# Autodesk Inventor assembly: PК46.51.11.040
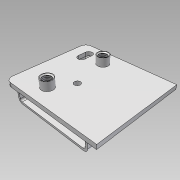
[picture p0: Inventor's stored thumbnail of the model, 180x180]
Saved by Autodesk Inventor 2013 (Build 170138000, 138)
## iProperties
Shininess: 64.0
Length Units: 11269
Angle Units: 11279
Time Units: 11290
Mass Units: 11283
Length Display Precision: 3
Angle Display Precision: 2
Compacted: True
Created: 2005-02
Part Number: PК46.51.11.040
Document SubType Name: Assembly
Designer: =<Author>
Manufacturer: Standard
Standards Organization: Custom
Description: Reliance Lock
Mass: 287.102 g
Surface Area: 258.181 cm^2
Volume: 36.5269 cm^3
Density: 7.86 g/cm^3
Density: 0.0
Volumn: 0.0
Area: 0.0
PropertySet Name: Model Information
Control State: 0
Master: False
Checked Out: False
Checked Out Date: 2008-10-15
Last Check In Date: 2008-10-15
Author: PVitaliy
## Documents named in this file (4)
- Y:\Dropbox\Launch 2013\Eco Material Advisor\Assy, Door\_Data\Assy, Cab\PK46.51.11.040.iam
- Y:\Dropbox\Launch 2013\Eco Material Advisor\Assy, Door\_Data\Assy, Cab\PK46.51.11.041.ipt
- Y:\Dropbox\Launch 2013\Eco Material Advisor\Assy, Door\_Data\Assy, Cab\PK46.51.11.044.ipt
- Y:\Dropbox\Launch 2013\Eco Material Advisor\Assy, Door\_Data\Assy, Cab\PK46.51.11.042.ipt
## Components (5 placed, 3 different names)
1. ПК46.51.11.041:1 — Mate:1, Flush:2, Flush:3, Mate:2, Flush:4, Insert:1, Insert:2
2. PK46.51.11.044:1 — Flush:1, Mate:1, Flush:2, Flush:3
3. PK46.51.11.044:2 — Flush:1, Mate:2, Flush:4
4. PK46.51.11.042:1 — Insert:1
5. PK46.51.11.042:2 — Insert:2
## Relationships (8: Flush 4, Mate 2, Insert 2)
- Flush:1: PK46.51.11.044:1 ↔ PK46.51.11.044:2
- Mate:1: ПК46.51.11.041:1 ↔ PK46.51.11.044:1
- Flush:2: ПК46.51.11.041:1 ↔ PK46.51.11.044:1
- Flush:3: ПК46.51.11.041:1 ↔ PK46.51.11.044:1
- Mate:2: ПК46.51.11.041:1 ↔ PK46.51.11.044:2
- Flush:4: ПК46.51.11.041:1 ↔ PK46.51.11.044:2
- Insert:1: ПК46.51.11.041:1 ↔ PK46.51.11.042:1
- Insert:2: ПК46.51.11.041:1 ↔ PK46.51.11.042:2
